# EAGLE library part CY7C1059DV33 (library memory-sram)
Source: CYPRESS cy7c1059dv33_8.pdf
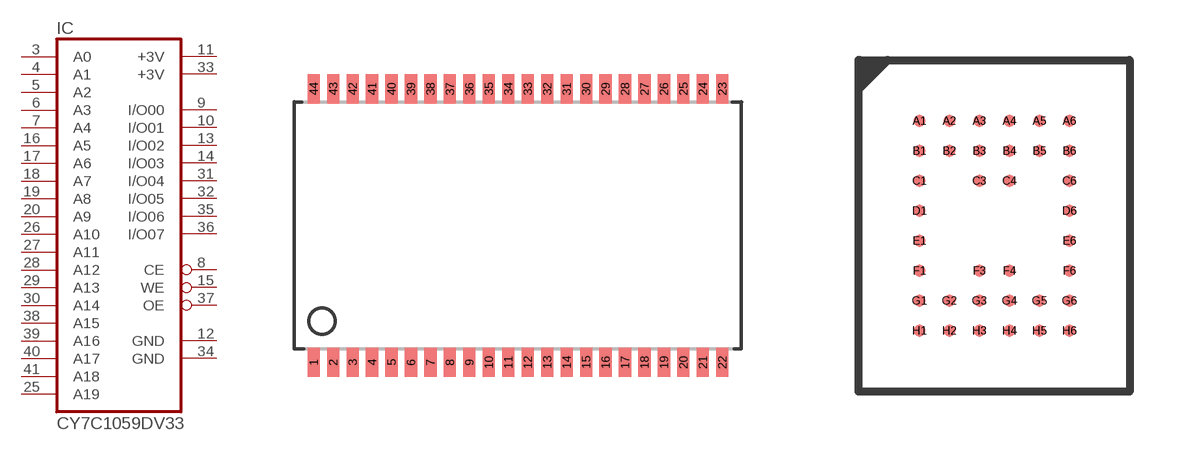
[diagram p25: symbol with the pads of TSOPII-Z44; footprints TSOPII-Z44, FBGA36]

Designator prefix IC

## CY7C1059DV33-10ZSXI  [TSOPII-Z44]
3  A0  in
4  A1  in
5  A2  in
6  A3  in
7  A4  in
8  CE  in
9  I/O00
10  I/O01
11  +3V  pwr
12  GND  pwr
13  I/O02
14  I/O03
15  WE  in
16  A5  in
17  A6  in
18  A7  in
19  A8  in
20  A9  in
25  A19  in
26  A10  in
27  A11  in
28  A12  in
29  A13  in
30  A14  in
31  I/O04
32  I/O05
33  +3V  pwr
34  GND  pwr
35  I/O06
36  I/O07
37  OE  in
38  A15  in
39  A16  in
40  A17  in
41  A18  in

## CY7C1059DV33-10BAXI  [FBGA36]
A1  A0  in
A2  A1  in
A4  A3  in
A5  A6  in
A6  A8  in
B1  I/O04
B2  A2  in
B3  WE  in
B4  A4  in
B5  A7  in
B6  I/O00
C1  I/O05
C3  A19  in
C4  A5  in
C6  I/O01
D1  GND  pwr
D6  +3V  pwr
E1  +3V  pwr
E6  GND  pwr
F1  I/O06
F3  A18  in
F4  A17  in
F6  I/O02
G1  I/O07
G2  OE  in
G3  CE  in
G4  A16  in
G5  A15  in
G6  I/O03
H1  A9  in
H2  A10  in
H3  A11  in
H4  A12  in
H5  A13  in
H6  A14  in

## Footprint TSOPII-Z44 (pad centres in mm)
44 PIN TSOP II Z44 Source: CYPRESS cy7c1049cv33_8.pdf
smd 0.5 x 1.2: 1 -8.4,-5.627; 2 -7.6,-5.627; 3 -6.8,-5.627; 4 -6,-5.627; 5 -5.2,-5.627; 6 -4.4,-5.627; 7 -3.6,-5.627; 8 -2.8,-5.627; 9 -2,-5.627; 10 -1.2,-5.627; 11 -0.4,-5.627; 12 0.4,-5.627; 13 1.2,-5.627; 14 2,-5.627; 15 2.8,-5.627; 16 3.6,-5.627; 17 4.4,-5.627; 18 5.2,-5.627; 19 6,-5.627; 20 6.8,-5.627; 21 7.6,-5.627; 22 8.4,-5.627; 23 8.4,5.627; 24 7.6,5.627; 25 6.8,5.627; 26 6,5.627; 27 5.2,5.627; 28 4.4,5.627; 29 3.6,5.627; 30 2.8,5.627; 31 2,5.627; 32 1.2,5.627; 33 0.4,5.627; 34 -0.4,5.627; 35 -1.2,5.627; 36 -2,5.627; 37 -2.8,5.627; 38 -3.6,5.627; 39 -4.4,5.627; 40 -5.2,5.627; 41 -6,5.627; 42 -6.8,5.627; 43 -7.6,5.627; 44 -8.4,5.627

## Footprint FBGA36 (pad centres in mm)
36-Ball FBGA (7.00 mm x 8.5 mm x 1.2 mm) (51-85105) Source: CYPRESS cy7c1059dv33_8.pdf
smd 0.3 x 0.3: A1 -1.875,2.625; A2 -1.125,2.625; A3 -0.375,2.625; A4 0.375,2.625; A5 1.125,2.625; A6 1.875,2.625; B1 -1.875,1.875; B2 -1.125,1.875; B3 -0.375,1.875; B4 0.375,1.875; B5 1.125,1.875; B6 1.875,1.875; C1 -1.875,1.125; C3 -0.375,1.125; C4 0.375,1.125; C6 1.875,1.125; D1 -1.875,0.375; D6 1.875,0.375; E1 -1.875,-0.375; E6 1.875,-0.375; F1 -1.875,-1.125; F3 -0.375,-1.125; F4 0.375,-1.125; F6 1.875,-1.125; G1 -1.875,-1.875; G2 -1.125,-1.875; G3 -0.375,-1.875; G4 0.375,-1.875; G5 1.125,-1.875; G6 1.875,-1.875; H1 -1.875,-2.625; H2 -1.125,-2.625; H3 -0.375,-2.625; H4 0.375,-2.625; H5 1.125,-2.625; H6 1.875,-2.625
